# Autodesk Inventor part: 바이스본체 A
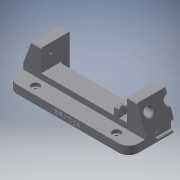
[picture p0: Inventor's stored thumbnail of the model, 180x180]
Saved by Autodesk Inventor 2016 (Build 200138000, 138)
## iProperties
Created: 2017-04
Part Number: 바이스본체 A
Material: 알루미늄 6061
Document SubType Name: Modeling
Designer: mduedu
Density: 2.71 g/cm^3
Appearance: 기본값
Mass: 324.154 g
Surface Area: 276.938 cm^2
Volume: 119.614 cm^3
Author: mduedu
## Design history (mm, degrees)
sketch "스케치1"
  geometry: L1 (-75, 0)-(75, 0); L2 (-75, 0)-(-75, 17); L3 (-53, 17)-(53, 17); L4 (75, 17)-(75, 0); L5 (-75, 17)-(-65.173, 44); L6 (-65.173, 44)-(-53, 44); L7 (-53, 44)-(-53, 17); L8 (0, 0)-(0, 17); L9 (75, 17)-(65.173, 44); L10 (65.173, 44)-(53, 44); L11 (53, 44)-(53, 17); 1 further point
  constraints: 22 end point, 4 perpendicular, 2 horizontal alignment, 2 midpoint, 2 symmetric about line, 1 coincident, 1 collinear, 1 horizontal, 1 vertical
  dimensions: "d0" = 150 distance of L1.start L1.end; "d1" = 17 distance of L1.start L2.end; "d2" = 27 distance of L3.start L6.end; "d3" = 22 distance of L3.start L2.end; "d4" = 70 deg angle of L3 L5; "d54" = 20 deg angle of L9 L4
extrude "돌출1" new body sketch "스케치1" stored distance "d5" = 70; taper "d6" = 0 deg
sketch "스케치2"
  geometry: L1 (0, 70)-(106, 70) reference; L2 (106, 70)-(106, 0) reference; L3 (106, 0)-(0, 0) reference; L4 (0, 47)-(106, 47); L5 (106, 47)-(106, 23); L6 (106, 23)-(0, 23); L7 (0, 23)-(0, 47); L8 (0, 70)-(0, 0) reference; 2 further points
  constraints: 8 end point, 2 parallel, 2 point on line, 1 horizontal, 1 horizontal alignment, 1 midpoint, 1 perpendicular
  dimensions: "d7" = 24 distance between parallel lines of L6 L4
extrude "돌출2" cut sketch "스케치2" stored distance "d9" = 70; taper "d10" = 0 deg
sketch "스케치3"
  geometry: L1 (22, -23)-(128, -23) reference; L2 (128, -47)-(22, -47) reference; L3 (22, -18)-(128, -18); L4 (128, -52)-(22, -52); L5 (22, -18)-(22, -52); L6 (128, -18)-(128, -52); 1 further point
  constraints: 8 end point, 3 parallel, 2 point on line, 1 perpendicular
  dimensions: "d11" = 5 distance between parallel lines of L3 L1; "d12" = 5 distance between parallel lines of L4 L2
extrude "돌출3" cut sketch "스케치3" distance "d13" = 12; taper "d14" = 0 deg
fillet "모깎기1" dims "d15" = 3, "d16" = 3
sketch "스케치4"
  geometry: L1 (103, 23)-(3, 23) reference; L2 (0, 26)-(0, 0) reference; L3 (106, 0)-(0, 0) reference; L4 (106, 26)-(106, 0) reference; L5 (96, 0)-(90, 0); L6 (90, 0)-(90, 19.5); L7 (96, 19.5)-(96, 0); L8 (90, 19.5)-(96, 19.5); A1 r 3 centre (3, 26) between (0, 26) and (3, 23) reference; A2 r 3 centre (103, 26) between (103, 23) and (106, 26) reference; 1 further point
  constraints: 8 end point, 2 perpendicular, 1 horizontal, 1 parallel, 1 point on line
  dimensions: "d17" = 10 distance between parallel lines of L7 L4; "d18" = 6 distance between parallel lines of L7 L6; "d27" = 3.5 distance between parallel lines of L8 L1
extrude "돌출4" join sketch "스케치4" distance "d19" = 12; taper "d20" = 0 deg
chamfer "모따기1" distance "d21" = 3; stored, may be unused: second distance "d22" = 2, angle "d23" = 45 deg
chamfer "모따기2" distance "d24" = 3; stored, may be unused: second distance "d25" = 2, angle "d26" = 45 deg
sketch "스케치5"
  geometry: L1 (-15.5, 35.8)-(-15.5, -25.8) reference; L2 (19.5, 0)-(0, 0) reference; C1 r 6.5 at (9.5, 15); 1 further point
  constraints: 1 centre point
  dimensions: "d28" = 13 diameter of C1; "d30" = 15 distance from line of C1.centre L2; "d31" = 25 distance from line of C1.centre L1
extrude "돌출5" cut sketch "스케치5" stored distance "d32" = 12; taper "d33" = 0 deg
sketch "스케치6"
  geometry: C1 r 5 at (-10, 15); C2 r 5 at (-60, 15); A1 r 6.5 centre (-10, 15) between (-15.766, 12) and (-4.234, 12) reference; A2 r 6.5 centre (-60, 15) between (-65.766, 12) and (-54.234, 12) reference; 1 further point
  constraints: 2 centre point, 2 coincident
  dimensions: "d34" = 10 diameter of C1; "d35" = 10 diameter of C2 (= d34)
extrude "돌출6" cut sketch "스케치6" stored distance "d36" = 12; taper "d37" = 0 deg
chamfer "모따기3" distance "d38" = 1; stored, may be unused: second distance "d39" = 2, angle "d40" = 45 deg
chamfer "모따기4" distance "d41" = 1; stored, may be unused: second distance "d42" = 2, angle "d43" = 45 deg
sketch "스케치7"
  geometry: L1 (-35, 35.8)-(-35, -25.8) reference; L2 (-70, 0)-(0, 0) reference; C1 r 5 at (-35, 15); 1 further point
  constraints: 1 centre point, 1 point on line
  dimensions: "d44" = 10 diameter of C1; "d45" = 15 distance from line of C1.centre L2
extrude "돌출7" cut sketch "스케치7" stored distance "d46" = 12; taper "d47" = 0 deg
chamfer "모따기5" distance "d48" = 1; stored, may be unused: second distance "d49" = 2, angle "d50" = 45 deg
node "작업축1"
sketch "스케치8"
  geometry: L1 (-105, 32)-(105, 32) reference; L2 (58, 32)-(64, 32); L3 (64, 32)-(64, 40); L4 (64, 40)-(58, 40); L5 (58, 40)-(58, 32); L6 (53, 38)-(53, 26) reference; 1 further point
  constraints: 8 end point, 2 parallel, 1 horizontal, 1 perpendicular, 1 point on line
  dimensions: "d51" = 5 distance from line of L6 L2.start; "d52" = 6 distance of L3.end L4.end; "d53" = 16 diameter of L4 L1
revolve "회전1" sketch "스케치8" stored, may be unused: angle "d55" = 90 deg
fillet "모깎기2"
chamfer "모따기6" distance "d56" = 1; stored, may be unused: second distance "d57" = 2, angle "d58" = 45 deg
sketch "스케치9"
  geometry: L1 (17.5, 3)-(52.5, 3); L2 (52.5, 13)-(17.5, 13); L3 (70, 0)-(0, 0) reference; L4 (17.5, 8)-(52.5, 8); A1 r 5 centre (17.5, 8) between (17.5, 13) and (17.5, 3); A2 r 5 centre (52.5, 8) between (52.5, 3) and (52.5, 13); 3 further points
  constraints: 6 end point, 4 point on circle, 3 tangent, 2 centre point, 2 midpoint, 2 parallel, 1 horizontal, 1 vertical alignment
  dimensions: "d59" = 35 distance of L4.start L4.end; "d61" = 5 radius of A2; "d62" = 8 distance between parallel lines of L3 L4
extrude "돌출8" cut sketch "스케치9" distance "d63" = 3; taper "d64" = 0 deg
chamfer "모따기7" distance "d65" = 1; stored, may be unused: second distance "d66" = 2, angle "d67" = 45 deg
chamfer "모따기8" distance "d68" = 1; stored, may be unused: second distance "d69" = 2, angle "d70" = 45 deg
feature "분할1"
sketch "스케치10"
  geometry: L1 (35, 27)-(0, 27) reference; L2 (0, 0)-(0, 27) reference; 1 further point
  dimensions: "d85" = 11.5 distance from line of point (12, 15.5) L1; "d86" = 12 distance from line of point (12, 15.5) L2
hole "구멍1" sketch "스케치10" at (12, 15.5) diameter "d71" = 3.242; stored, may be unused: countersink angle "d75" = 90 deg, drill point angle "d77" = 120 deg; dims "d72" = 8, "d73" = 4, "d74" = 2, "d76" = 10
sketch "스케치11"
  geometry: A1 r 5 centre (17.5, 8) between (17.5, 13) and (17.5, 3) reference; 1 further point
  constraints: 1 coincident
hole "구멍3" sketch "스케치11" at (17.5, 8) diameter "d78" = 2.459; stored, may be unused: countersink angle "d82" = 90 deg, drill point angle "d84" = 120 deg; dims "d79" = 4.5, "d80" = 4, "d81" = 2, "d83" = 6
sketch "스케치13"
  geometry: L1 (75, 0)-(75, 35) reference; L2 (-75, 0)-(-75, 35) reference; L3 (-75, 35)-(75, 35); L4 (75, 35)-(75, 55); L5 (75, 55)-(-75, 55); L6 (-75, 55)-(-75, 35); 1 further point
  constraints: 8 end point, 2 parallel, 1 horizontal, 1 perpendicular, 1 point on line
  dimensions: "d90" = 20 distance between parallel lines of L5 L3; "d94" = 150 distance of L4.end L5.end (derived)
extrude "돌출9" join sketch "스케치13" distance "d92" = 10; taper "d93" = 0 deg
sketch "스케치14"
  geometry: L1 (-75, -35)-(-75, -55) reference; L2 (75, -55)-(75, -35) reference; L3 (-75, -45)-(75, -45); 3 further points
  constraints: 2 end point, 2 midpoint, 2 point on line
  dimensions: "d95" = 50 horizontal distance of point (-50, -45) point (0, 0); "d96" = 100 distance of point (50, -45) point (-50, -45)
fillet "모깎기3" dims "d97" = 12
chamfer "모따기9" distance "d98" = 1; stored, may be unused: second distance "d99" = 2, angle "d100" = 45 deg
hole "구멍4" sketch "스케치14" diameter "d101" = 4.134; stored, may be unused: countersink angle "d105" = 90 deg, drill point angle "d107" = 118 deg; dims "d102" = 6, "d103" = 10, "d104" = 4, "d106" = 8
sketch "스케치15"
  geometry: L1 (0, 0)-(126, 0) reference; 3 further points
  constraints: 1 midpoint, 1 vertical alignment, 1 other
  dimensions: "d109" = 5 distance from line of point (63, 5) L1
feature "엠보싱2" sketch "스케치15" dims "d0" = 150, "d1" = 17, "d2" = 27, "d3" = 22, "d4" = 70 deg, "d54" = 20 deg, "d110" = 0.5, "d111" = 0
node "솔리드1"
mirror "대칭1"
mirror "대칭2"
mirror "대칭3"
mirror "대칭4"
node "투영된 루프1"
